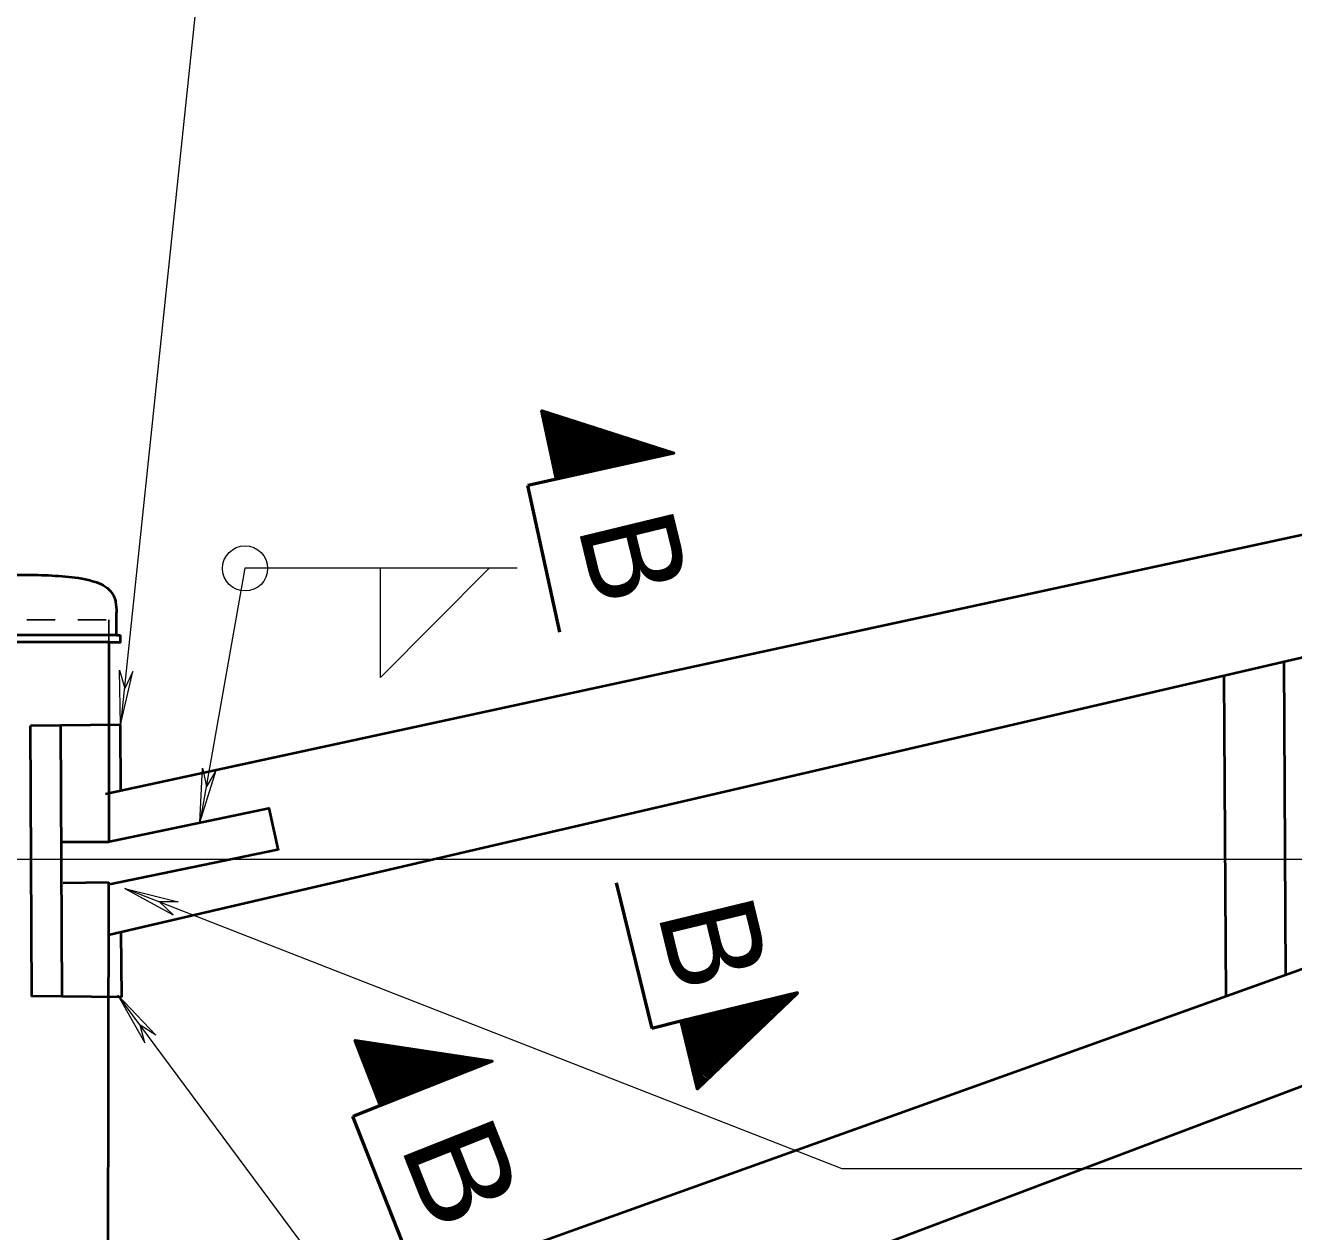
# Model space of a CAD drawing. Extents: x 312583 to 312854, y 144418 to 144597.
# Drawn here: x 312635.77 to 312655.88, y 144541.61 to 144560.74 of the extents above; entities that cross this region are included whole.
import ezdxf
from ezdxf.enums import TextEntityAlignment as Align

# ---------------------------------------------------------------- set-up
doc = ezdxf.new("R2010")
doc.units = 0
doc.header["$LTSCALE"] = 0.3
doc.linetypes.add('SHORT_DASHED', pattern=[2.7, 1.5, -1.2])
doc.layers.add('1', color=7, linetype='Continuous', lineweight=35)

msp = doc.modelspace()

# ---------------------------------------------------------------- linework, layer by layer
at = {"layer": '1', "lineweight": 40}
for p, q in [((312642.9736, 144549.8358), (312705.979, 144563.4998)), ((312642.9736, 144547.6856), (312698.2854, 144560.5489)), ((312642.9736, 144541.1052), (312695.2125, 144559.8246)), ((312642.9736, 144539.0007), (312695.3421, 144558.7723)), ((312637.2168, 144551.071), (312637.2168, 144551.4294)), ((312637.2168, 144551.071), (312633.999, 144551.071)), ((312637.0948, 144550.9567), (312635.6384, 144550.9567)), ((312637.0948, 144550.9567), (312637.0948, 144547.7923)), ((312637.2168, 144551.071), (312637.2778, 144551.071)), ((312655.7531, 144545.6726), (312655.7302, 144550.6593)), ((312654.8076, 144545.3447), (312654.7771, 144550.4153)), ((312637.0414, 144548.5548), (312642.9736, 144549.8358)), ((312637.2778, 144549.6452), (312635.8519, 144549.6299)), ((312636.3551, 144545.3447), (312636.3322, 144549.6299)), ((312637.2854, 144548.5929), (312637.2778, 144549.6452)), ((312636.3399, 144547.7923), (312637.0948, 144547.7923)), ((312637.0795, 144547.1137), (312639.7711, 144547.6703)), ((312637.11, 144546.3207), (312642.9736, 144547.6856)), ((312636.3704, 144547.1442), (312637.0871, 144547.1518)), ((312637.0871, 144547.1518), (312637.0642, 144528.44)), ((312637.2854, 144546.3588), (312637.293, 144545.3294))]:
    msp.add_line(p, q, dxfattribs=at)
at = {"layer": '1', "lineweight": 13}
for p, q in [((312638.6579, 144562.8059), (312637.2778, 144549.6452)), ((312639.2526, 144552.1309), (312638.5359, 144548.0973)), ((312643.5684, 144552.1309), (312639.2526, 144552.1309)), ((312637.2625, 144550.5144), (312637.3464, 144550.2247)), ((312637.2778, 144549.6452), (312637.2625, 144550.5144)), ((312637.2778, 144549.6452), (312637.476, 144550.4916)), ((312637.476, 144550.4916), (312637.3464, 144550.2247)), ((312638.5359, 144548.0973), (312638.5816, 144548.9589)), ((312638.5816, 144548.9589), (312638.6426, 144548.6692)), ((312638.5359, 144548.0973), (312638.7951, 144548.9284)), ((312638.7951, 144548.9284), (312638.6426, 144548.6692)), ((312740.9778, 144547.5102), (312630.9044, 144547.5102)), ((312648.7229, 144542.6073), (312637.3464, 144547.0527)), ((312637.3464, 144547.0527), (312638.1165, 144546.6333)), ((312637.3464, 144547.0527), (312638.1928, 144546.8392)), ((312638.1165, 144546.6333), (312637.8954, 144546.8392)), ((312638.1928, 144546.8392), (312637.8954, 144546.8392)), ((312642.7068, 144537.9866), (312637.2396, 144545.3599)), ((312637.2396, 144545.3599), (312637.6666, 144544.605)), ((312637.2396, 144545.3599), (312637.842, 144544.727)), ((312637.6666, 144544.605), (312637.5904, 144544.8872)), ((312637.842, 144544.727), (312637.5904, 144544.8872)), ((312669.3332, 144542.6073), (312648.7229, 144542.6073))]:
    msp.add_line(p, q, dxfattribs=at)
at = {"layer": '1'}
for p, q in [((312643.9649, 144554.5938), (312643.9801, 144554.609)), ((312643.9725, 144554.548), (312644.003, 144554.609)), ((312643.9878, 144554.4947), (312644.0182, 144554.5938)), ((312643.9954, 144554.4489), (312644.0411, 144554.5862)), ((312644.0106, 144554.3956), (312644.0716, 144554.5862)), ((312644.0182, 144554.3574), (312644.0869, 144554.5709)), ((312644.0259, 144554.3117), (312644.1098, 144554.5709)), ((312644.0335, 144554.2659), (312644.1402, 144554.5557)), ((312644.0488, 144554.2202), (312644.1555, 144554.5557)), ((312644.0564, 144554.1744), (312644.186, 144554.548)), ((312644.0716, 144554.121), (312644.2012, 144554.5404)), ((312644.0792, 144554.0753), (312644.2318, 144554.5328)), ((312644.0869, 144554.0296), (312644.2546, 144554.5328)), ((312644.1021, 144553.9838), (312644.2699, 144554.5176)), ((312644.1098, 144553.938), (312644.2928, 144554.5176)), ((312644.1174, 144553.8923), (312644.3156, 144554.5023)), ((312644.1326, 144553.8389), (312644.3385, 144554.4947)), ((312644.1402, 144553.7932), (312644.3614, 144554.4947)), ((312644.1479, 144553.7474), (312644.3766, 144554.4794)), ((312644.1631, 144553.7017), (312644.4071, 144554.4718)), ((312644.1708, 144553.6559), (312644.43, 144554.4642)), ((312644.1784, 144553.6178), (312644.4452, 144554.4566)), ((312644.1936, 144553.5644), (312644.4758, 144554.4566)), ((312644.2089, 144553.5492), (312644.4986, 144554.4413)), ((312644.2394, 144553.5492), (312644.5215, 144554.4413)), ((312644.2699, 144553.5568), (312644.5444, 144554.4337)), ((312644.2928, 144553.5644), (312644.5672, 144554.426)), ((312644.3232, 144553.572), (312644.5901, 144554.4184)), ((312644.3461, 144553.5797), (312644.613, 144554.4184)), ((312644.3766, 144553.5873), (312644.6282, 144554.4032)), ((312644.3995, 144553.5873), (312644.6588, 144554.4032)), ((312644.43, 144553.5949), (312644.6816, 144554.3879)), ((312644.4605, 144553.6026), (312644.6969, 144554.3803)), ((312644.4758, 144553.6026), (312644.7198, 144554.3727)), ((312644.5062, 144553.6102), (312644.7502, 144554.365)), ((312644.5368, 144553.6178), (312644.7731, 144554.3574)), ((312644.5596, 144553.6254), (312644.7884, 144554.3498)), ((312644.5901, 144553.633), (312644.8189, 144554.3422)), ((312644.6206, 144553.633), (312644.8418, 144554.3422)), ((312644.6435, 144553.6407), (312644.857, 144554.3269)), ((312644.6664, 144553.6483), (312644.8799, 144554.3269)), ((312644.6969, 144553.6483), (312644.9104, 144554.3117)), ((312644.7274, 144553.6559), (312644.9256, 144554.3117)), ((312644.7579, 144553.6636), (312644.9485, 144554.304)), ((312644.7808, 144553.6712), (312644.9714, 144554.2964)), ((312644.8036, 144553.6788), (312644.9942, 144554.2888)), ((312644.8265, 144553.6864), (312645.0248, 144554.2888)), ((312644.857, 144553.6864), (312645.04, 144554.2736)), ((312644.8799, 144553.694), (312645.0705, 144554.2659)), ((312644.9104, 144553.7017), (312645.0934, 144554.2659)), ((312644.9409, 144553.7093), (312645.1086, 144554.2507)), ((312644.9638, 144553.7093), (312645.1315, 144554.2507)), ((312644.9942, 144553.7169), (312645.162, 144554.2354)), ((312645.0248, 144553.7246), (312645.1772, 144554.2354)), ((312645.0476, 144553.7322), (312645.2001, 144554.2202)), ((312645.0781, 144553.7322), (312645.223, 144554.2202)), ((312645.101, 144553.7398), (312645.2459, 144554.2126)), ((312645.1239, 144553.7474), (312645.2688, 144554.2049)), ((312645.1468, 144553.7474), (312645.2916, 144554.1973)), ((312645.1772, 144553.755), (312645.3145, 144554.1973)), ((312645.2078, 144553.7627), (312645.3374, 144554.182)), ((312645.2382, 144553.7703), (312645.3602, 144554.1744)), ((312645.2611, 144553.7779), (312645.3831, 144554.1744)), ((312645.2916, 144553.7856), (312645.406, 144554.1592)), ((312645.3145, 144553.7856), (312645.4289, 144554.1516)), ((312645.345, 144553.7932), (312645.4518, 144554.1439)), ((312645.3679, 144553.8008), (312645.4746, 144554.1363)), ((312645.3984, 144553.8084), (312645.4975, 144554.1287)), ((312645.4212, 144553.816), (312645.5204, 144554.121)), ((312645.4441, 144553.816), (312645.5356, 144554.121)), ((312645.4746, 144553.8237), (312645.5738, 144554.1134)), ((312645.4975, 144553.8313), (312645.589, 144554.1058)), ((312645.528, 144553.8389), (312645.6119, 144554.0982)), ((312645.5585, 144553.8389), (312645.6348, 144554.0906)), ((312645.5814, 144553.8466), (312645.6576, 144554.0829)), ((312645.6119, 144553.8542), (312645.6805, 144554.0829)), ((312645.6348, 144553.8542), (312645.7034, 144554.0677)), ((312645.6652, 144553.8618), (312645.7186, 144554.06)), ((312645.6958, 144553.8694), (312645.7491, 144554.0524)), ((312645.7262, 144553.877), (312645.772, 144554.0448)), ((312645.7415, 144553.8847), (312645.7872, 144554.0372)), ((312645.772, 144553.8923), (312645.8178, 144554.0296)), ((312645.7949, 144553.8923), (312645.8406, 144554.0219)), ((312645.8178, 144553.8999), (312645.8635, 144554.0219)), ((312645.8482, 144553.9076), (312645.8788, 144554.0067)), ((312645.8788, 144553.9152), (312645.9092, 144554.0067)), ((312645.9092, 144553.9152), (312645.9321, 144553.9914)), ((312645.9321, 144553.9228), (312645.9474, 144553.9914)), ((312645.9626, 144553.9304), (312645.9702, 144553.9762)), ((312645.9855, 144553.938), (312646.0008, 144553.9762)), ((312646.016, 144553.9457), (312646.016, 144553.9686)), ((312646.0465, 144553.9457), (312646.0389, 144553.9609)), ((312647.7011, 144545.3218), (312647.8079, 144545.2074)), ((312647.7316, 144545.3294), (312647.8308, 144545.215)), ((312647.7545, 144545.3294), (312647.846, 144545.2379)), ((312647.7774, 144545.337), (312647.8689, 144545.2532)), ((312647.8079, 144545.3447), (312647.8765, 144545.2684)), ((312647.8384, 144545.3523), (312647.8994, 144545.2837)), ((312647.8612, 144545.3599), (312647.9222, 144545.2989)), ((312647.8841, 144545.3676), (312647.9299, 144545.3142)), ((312647.9146, 144545.3752), (312647.9528, 144545.3294)), ((312647.9375, 144545.3752), (312647.968, 144545.3447)), ((312647.968, 144545.3828), (312647.9832, 144545.3676)), ((312647.9985, 144545.3904), (312647.9985, 144545.3752)), ((312646.9005, 144545.1236), (312647.2894, 144544.7118)), ((312646.9234, 144545.1312), (312647.3122, 144544.727)), ((312646.9539, 144545.1388), (312647.3351, 144544.7423)), ((312646.9844, 144545.1464), (312647.3428, 144544.7576)), ((312647.0072, 144545.154), (312647.3656, 144544.7728)), ((312647.0378, 144545.1617), (312647.3809, 144544.788)), ((312647.0682, 144545.1617), (312647.3961, 144544.8033)), ((312647.0835, 144545.1693), (312647.419, 144544.8186)), ((312647.1064, 144545.1769), (312647.4342, 144544.8414)), ((312647.1369, 144545.1846), (312647.4571, 144544.849)), ((312647.1674, 144545.1922), (312647.4648, 144544.8719)), ((312647.1979, 144545.1998), (312647.4876, 144544.8872)), ((312647.2208, 144545.1998), (312647.5029, 144544.9024)), ((312647.2512, 144545.2074), (312647.5181, 144544.9253)), ((312647.2741, 144545.215), (312647.5334, 144544.9406)), ((312647.3046, 144545.2227), (312647.5562, 144544.9558)), ((312647.3275, 144545.2303), (312647.5639, 144544.971)), ((312647.3504, 144545.2379), (312647.5868, 144544.9863)), ((312647.3809, 144545.2456), (312647.602, 144545.0092)), ((312647.4038, 144545.2456), (312647.6172, 144545.0168)), ((312647.4342, 144545.2532), (312647.6478, 144545.0397)), ((312647.4571, 144545.2608), (312647.6554, 144545.0473)), ((312647.4876, 144545.2684), (312647.6782, 144545.0702)), ((312647.5181, 144545.276), (312647.6935, 144545.0854)), ((312647.541, 144545.2837), (312647.7088, 144545.1007)), ((312647.5715, 144545.2913), (312647.7316, 144545.1159)), ((312647.5944, 144545.2913), (312647.7469, 144545.1312)), ((312647.6172, 144545.2989), (312647.7545, 144545.154)), ((312647.6478, 144545.3066), (312647.7774, 144545.1693)), ((312647.6782, 144545.3142), (312647.8002, 144545.1846)), ((312646.1685, 144544.9253), (312646.8166, 144544.2467)), ((312646.1761, 144544.9482), (312646.8242, 144544.2696)), ((312646.2066, 144544.9558), (312646.8471, 144544.2772)), ((312646.2371, 144544.9634), (312646.87, 144544.3)), ((312646.26, 144544.971), (312646.8776, 144544.3153)), ((312646.2905, 144544.9787), (312646.9005, 144544.3306)), ((312646.3134, 144544.9787), (312646.9158, 144544.3458)), ((312646.3439, 144544.9787), (312646.931, 144544.361)), ((312646.3591, 144544.9939), (312646.9539, 144544.3763)), ((312646.3896, 144545.0016), (312646.9691, 144544.3992)), ((312646.4201, 144545.0092), (312646.9768, 144544.4144)), ((312646.443, 144545.0168), (312646.9996, 144544.4297)), ((312646.4735, 144545.0244), (312647.0225, 144544.4449)), ((312646.504, 144545.032), (312647.0378, 144544.4678)), ((312646.5269, 144545.032), (312647.053, 144544.483)), ((312646.5574, 144545.032), (312647.0682, 144544.4983)), ((312646.5802, 144545.0473), (312647.0911, 144544.5136)), ((312646.6031, 144545.0549), (312647.0988, 144544.5288)), ((312646.626, 144545.0626), (312647.1216, 144544.544)), ((312646.6565, 144545.0702), (312647.1369, 144544.5669)), ((312646.687, 144545.0702), (312647.1521, 144544.5746)), ((312646.7175, 144545.0778), (312647.175, 144544.5974)), ((312646.7404, 144545.0854), (312647.1902, 144544.605)), ((312646.7709, 144545.093), (312647.2055, 144544.6279)), ((312646.7938, 144545.093), (312647.2284, 144544.6432)), ((312646.8242, 144545.1083), (312647.2436, 144544.6584)), ((312646.8395, 144545.1083), (312647.2589, 144544.6813)), ((312646.87, 144545.1159), (312647.2818, 144544.6889)), ((312646.1761, 144544.8719), (312646.7861, 144544.2314)), ((312646.1914, 144544.8338), (312646.7785, 144544.2162)), ((312646.199, 144544.7804), (312646.7556, 144544.2009)), ((312646.2142, 144544.7347), (312646.7404, 144544.1857)), ((312641.0064, 144544.6127), (312641.014, 144544.6279)), ((312641.0216, 144544.5669), (312641.0369, 144544.6356)), ((312641.0445, 144544.5212), (312641.0598, 144544.6203)), ((312641.0598, 144544.4754), (312641.0902, 144544.6203)), ((312641.0826, 144544.4297), (312641.1131, 144544.6203)), ((312641.0979, 144544.3916), (312641.1284, 144544.6127)), ((312641.1131, 144544.3382), (312641.1512, 144544.6127)), ((312641.1284, 144544.3), (312641.1818, 144544.605)), ((312641.1512, 144544.2543), (312641.197, 144544.605)), ((312641.1665, 144544.2162), (312641.2351, 144544.605)), ((312641.1818, 144544.1628), (312641.2504, 144544.5974)), ((312641.197, 144544.1247), (312641.2732, 144544.5974)), ((312641.2199, 144544.0789), (312641.3038, 144544.5974)), ((312641.2351, 144544.0332), (312641.319, 144544.5898)), ((312641.258, 144543.9874), (312641.3419, 144544.5898)), ((312641.2732, 144543.9417), (312641.3648, 144544.5822)), ((312641.2885, 144543.8959), (312641.3876, 144544.5746)), ((312641.3114, 144543.8502), (312641.4181, 144544.5746)), ((312641.3266, 144543.812), (312641.4334, 144544.5669)), ((312641.3419, 144543.7663), (312641.4639, 144544.5593)), ((312641.3648, 144543.7206), (312641.4868, 144544.5593)), ((312641.3724, 144543.6824), (312641.502, 144544.5517)), ((312641.3952, 144543.629), (312641.5325, 144544.5593)), ((312641.4181, 144543.6138), (312641.5554, 144544.5517)), ((312641.4486, 144543.629), (312641.5782, 144544.5517)), ((312641.4715, 144543.6367), (312641.6088, 144544.544)), ((312641.4944, 144543.6443), (312641.624, 144544.544)), ((312641.5249, 144543.6596), (312641.6545, 144544.5364)), ((312641.5401, 144543.6748), (312641.6774, 144544.5364)), ((312641.5706, 144543.6824), (312641.6926, 144544.5288)), ((312641.5935, 144543.69), (312641.7155, 144544.5288)), ((312641.624, 144543.6977), (312641.746, 144544.5288)), ((312641.6545, 144543.7129), (312641.7612, 144544.5212)), ((312641.6698, 144543.7206), (312641.7918, 144544.5212)), ((312641.7002, 144543.7282), (312641.8146, 144544.5136)), ((312646.2219, 144544.6966), (312646.7251, 144544.1628)), ((312646.2295, 144544.6508), (312646.7099, 144544.1552)), ((312646.2448, 144544.5974), (312646.687, 144544.1323)), ((312646.26, 144544.5517), (312646.6794, 144544.117)), ((312641.7308, 144543.7434), (312641.8451, 144544.5059)), ((312641.7536, 144543.751), (312641.8604, 144544.5059)), ((312641.7765, 144543.7663), (312641.8909, 144544.4983)), ((312641.807, 144543.7739), (312641.9138, 144544.5059)), ((312641.8299, 144543.7816), (312641.929, 144544.4907)), ((312641.8528, 144543.7892), (312641.9595, 144544.4907)), ((312641.8756, 144543.7968), (312641.9824, 144544.4907)), ((312641.9061, 144543.812), (312641.9976, 144544.4907)), ((312641.9366, 144543.8197), (312642.0281, 144544.483)), ((312641.9595, 144543.8273), (312642.051, 144544.483)), ((312641.9824, 144543.8426), (312642.0662, 144544.4754)), ((312642.0052, 144543.8578), (312642.1044, 144544.4754)), ((312642.0358, 144543.8654), (312642.1196, 144544.4678)), ((312642.0586, 144543.873), (312642.1501, 144544.4678)), ((312642.0815, 144543.8807), (312642.173, 144544.4678)), ((312642.112, 144543.8959), (312642.1882, 144544.4602)), ((312642.1349, 144543.9036), (312642.2188, 144544.4602)), ((312642.1654, 144543.9112), (312642.2416, 144544.4526)), ((312642.1882, 144543.9264), (312642.2569, 144544.4526)), ((312642.2111, 144543.934), (312642.2874, 144544.4449)), ((312642.2416, 144543.9417), (312642.3102, 144544.4449)), ((312642.2645, 144543.9569), (312642.3331, 144544.4373)), ((312642.2874, 144543.9646), (312642.356, 144544.4373)), ((312642.3102, 144543.9722), (312642.3789, 144544.4373)), ((312642.3408, 144543.9798), (312642.4018, 144544.4373)), ((312642.3712, 144543.995), (312642.4246, 144544.4297)), ((312642.3941, 144544.0027), (312642.4551, 144544.422)), ((312642.417, 144544.0103), (312642.478, 144544.422)), ((312642.4475, 144544.0256), (312642.4932, 144544.4144)), ((312642.4628, 144544.0332), (312642.5238, 144544.4068)), ((312642.4932, 144544.0408), (312642.5466, 144544.4068)), ((312642.5161, 144544.056), (312642.5695, 144544.3992)), ((312642.5466, 144544.0637), (312642.5924, 144544.3992)), ((312642.5695, 144544.0789), (312642.6152, 144544.3992)), ((312642.5924, 144544.0866), (312642.6305, 144544.3916)), ((312642.6229, 144544.0942), (312642.6686, 144544.3916)), ((312642.6458, 144544.1018), (312642.6839, 144544.3916)), ((312642.6686, 144544.117), (312642.7144, 144544.3839)), ((312642.6991, 144544.1247), (312642.7372, 144544.3839)), ((312642.722, 144544.1323), (312642.7525, 144544.3763)), ((312642.7525, 144544.1476), (312642.783, 144544.3763)), ((312642.7678, 144544.1552), (312642.8059, 144544.3763)), ((312642.7982, 144544.1628), (312642.8288, 144544.3687)), ((312642.8288, 144544.178), (312642.8516, 144544.3687)), ((312642.8592, 144544.1857), (312642.8745, 144544.361)), ((312642.8745, 144544.1933), (312642.8974, 144544.3534)), ((312642.905, 144544.2086), (312642.9202, 144544.3534)), ((312642.9279, 144544.2162), (312642.9508, 144544.3458)), ((312642.9508, 144544.2238), (312642.9736, 144544.3458)), ((312642.9736, 144544.239), (312642.9965, 144544.3382)), ((312643.0041, 144544.2467), (312643.0194, 144544.3382)), ((312643.0346, 144544.2619), (312643.0422, 144544.3382)), ((312643.0575, 144544.2696), (312643.0575, 144544.3382)), ((312643.0804, 144544.2772), (312643.088, 144544.3306)), ((312643.1032, 144544.2848), (312643.1109, 144544.3306)), ((312643.1338, 144544.3), (312643.1338, 144544.3229)), ((312643.1642, 144544.3077), (312643.1566, 144544.3229)), ((312646.2676, 144544.5059), (312646.6565, 144544.1018)), ((312646.2829, 144544.4602), (312646.6412, 144544.0789)), ((312646.2905, 144544.4144), (312646.626, 144544.0713)), ((312646.2981, 144544.3687), (312646.6031, 144544.0484)), ((312646.3134, 144544.3153), (312646.5955, 144544.0408)), ((312646.321, 144544.2696), (312646.565, 144544.0179)), ((312646.3362, 144544.2314), (312646.5574, 144544.0027)), ((312646.3439, 144544.1857), (312646.5345, 144543.9874)), ((312646.3591, 144544.1323), (312646.5116, 144543.9722)), ((312646.3668, 144544.0942), (312646.504, 144543.9569)), ((312646.382, 144544.0408), (312646.4811, 144543.9417)), ((312646.3896, 144543.995), (312646.4659, 144543.9188)), ((312646.4049, 144543.9493), (312646.4506, 144543.9036)), ((312646.4125, 144543.9036), (312646.4354, 144543.8883))]:
    msp.add_line(p, q, dxfattribs=at)
at = {"layer": '1', "lineweight": 53}
for p, q in [((312644.1936, 144553.5416), (312643.7361, 144553.4424)), ((312644.247, 144551.1168), (312643.7361, 144553.4424)), ((312645.1391, 144547.1442), (312645.7034, 144544.8338)), ((312646.1609, 144544.9482), (312645.7034, 144544.8338)), ((312641.4029, 144543.6138), (312640.9606, 144543.4384)), ((312641.8375, 144541.2272), (312640.9606, 144543.4384))]:
    msp.add_line(p, q, dxfattribs=at)
at = {"layer": '1', "linetype": 'SHORT_DASHED', "lineweight": 25}
for p, q in [((312634.1744, 144551.315), (312637.0948, 144551.315)), ((312637.0948, 144551.315), (312637.0948, 144550.9567))]:
    msp.add_line(p, q, dxfattribs=at)
at = {"layer": '1', "lineweight": 53}
for points in [[(312644.1936, 144553.5416), (312643.9572, 144554.6243), (312646.0541, 144553.9533)], [(312646.1609, 144544.9482), (312646.4201, 144543.873), (312648.0138, 144545.398)], [(312641.4029, 144543.6138), (312640.9988, 144544.6432), (312643.1719, 144544.3153)]]:
    msp.add_lwpolyline(points, close=True, dxfattribs=at)
at = {"layer": '1', "lineweight": 13}
msp.add_lwpolyline([(312643.1261, 144552.1309), (312641.4029, 144550.4), (312641.4029, 144552.1309)], dxfattribs=at)
at = {"layer": '1', "lineweight": 40}
for points in [[(312637.0948, 144550.9567), (312637.2778, 144550.9567), (312637.2778, 144551.071)], [(312637.293, 144545.3294), (312635.8748, 144545.3447), (312635.8519, 144549.6299)], [(312637.0795, 144547.7923), (312639.6339, 144548.326), (312639.7788, 144547.655)]]:
    msp.add_lwpolyline(points, dxfattribs=at)
at = {"layer": '1', "lineweight": 13}
msp.add_circle((312639.2545, 144552.1281), 0.358, dxfattribs=at)
at = {"layer": '1', "lineweight": 40}
msp.add_spline([(312635.6384, 144552.0242), (312635.9739, 144552.0242), (312636.4085, 144552.0013), (312636.6144, 144551.9784), (312636.8202, 144551.9327), (312636.9728, 144551.8793), (312637.0948, 144551.7954), (312637.1862, 144551.6582), (312637.2015, 144551.5972), (312637.2168, 144551.4294)], degree=3, dxfattribs=at)

# ---------------------------------------------------------------- texts
at = {"layer": '1'}
for p in [(312644.6834, 144552.1358), (312645.9492, 144546.0053)]:
    msp.add_text('B', height=1.525, rotation=283.644, dxfattribs=at).set_placement(p, align=Align.CENTER)
at = {"layer": '1', "width": 1.15}
msp.add_text('B', height=1.525, rotation=291.625, dxfattribs=at).set_placement((312641.9844, 144542.2639), align=Align.CENTER)

doc.saveas('drawing.dxf')
